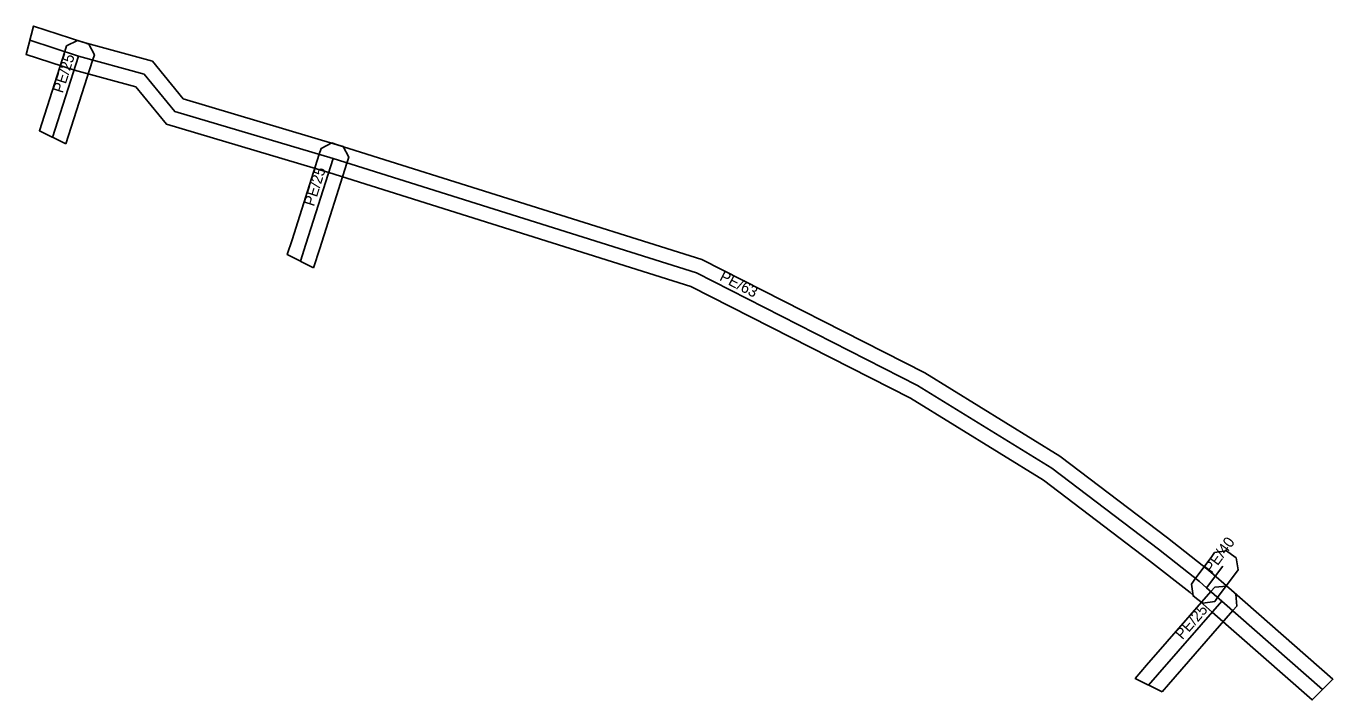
# Model space of a CAD drawing. Extents: x -897856 to -897764, y -995084 to -994957.
# Drawn here: x -897856.1 to -897766.3, y -995083.6 to -995037.3 of the extents above; entities that cross this region are included whole.
import ezdxf

# ---------------------------------------------------------------- set-up
doc = ezdxf.new("R2010")
doc.units = 0
for name, color, linetype in [('1', 7, 'Continuous'), ('24', 7, 'Continuous'), ('30', 7, 'Continuous')]:
    doc.layers.add(name, color=color, linetype=linetype)

msp = doc.modelspace()

# ---------------------------------------------------------------- linework, layer by layer
at = {"layer": '1'}
for points in [[(-897852.817, -995040.308), (-897856.141, -995039.231), (-897855.641, -995037.29), (-897852.243, -995038.392), (-897847.457, -995039.711), (-897845.341, -995042.299), (-897834.748, -995045.444), (-897809.68, -995053.331), (-897794.37, -995061.127), (-897785.074, -995066.864), (-897777.688, -995072.469), (-897774.849, -995074.712), (-897774.332, -995075.167), (-897773.282, -995076.077), (-897766.311, -995082.205), (-897767.728, -995083.622), (-897774.598, -995077.583), (-897775.648, -995076.673), (-897776.131, -995076.248), (-897778.912, -995074.051), (-897786.206, -995068.516), (-897795.35, -995062.873), (-897810.44, -995055.189), (-897835.332, -995047.356), (-897846.499, -995044.041), (-897848.603, -995041.469)], [(-897853.415, -995045.392), (-897855.225, -995044.487), (-897853.482, -995039.045), (-897853.356, -995038.651), (-897852.619, -995038.272), (-897852.225, -995038.398), (-897851.831, -995038.524), (-897851.452, -995039.261), (-897851.578, -995039.655)], [(-897836.38, -995053.91), (-897838.191, -995053.004), (-897837.863, -995051.977), (-897835.993, -995046.097), (-897835.867, -995045.702), (-897835.132, -995045.321), (-897834.737, -995045.447), (-897834.342, -995045.573), (-897833.961, -995046.308), (-897834.087, -995046.703), (-897835.957, -995052.583)], [(-897776.04, -995075.658), (-897775.794, -995075.325), (-897774.684, -995073.825), (-897774.438, -995073.492), (-897773.618, -995073.37), (-897773.285, -995073.616), (-897772.952, -995073.862), (-897772.83, -995074.682), (-897773.076, -995075.015), (-897774.186, -995076.515), (-897774.432, -995076.848), (-897775.252, -995076.97), (-897775.585, -995076.724), (-897775.918, -995076.478)], [(-897778.051, -995083.074), (-897779.897, -995082.152), (-897779.116, -995081.245), (-897774.694, -995076.173), (-897774.422, -995075.861), (-897773.595, -995075.804), (-897773.283, -995076.076), (-897772.971, -995076.348), (-897772.914, -995077.175), (-897773.186, -995077.487), (-897777.604, -995082.555)]]:
    msp.add_lwpolyline(points, close=True, dxfattribs=at)
at = {"layer": '24'}
for points in [[(-897855.891, -995038.261), (-897852.53, -995039.35), (-897848.03, -995040.59), (-897845.92, -995043.17), (-897835.04, -995046.4), (-897810.06, -995054.26), (-897794.86, -995062), (-897785.64, -995067.69), (-897778.3, -995073.26), (-897775.49, -995075.48), (-897774.99, -995075.92), (-897773.94, -995076.83), (-897767.02, -995082.914)], [(-897852.53, -995039.35), (-897854.32, -995044.94)], [(-897835.04, -995046.4), (-897836.91, -995052.28), (-897837.285, -995053.457)], [(-897774.99, -995075.92), (-897773.88, -995074.42)], [(-897773.94, -995076.83), (-897778.36, -995081.9), (-897778.974, -995082.613)]]:
    msp.add_lwpolyline(points, dxfattribs=at)

# ---------------------------------------------------------------- texts
at = {"layer": '30'}
for s, rotation, p in [('PE/25', 72.24365, (-897853.625, -995041.945)), ('PE/25', 72.35792, (-897836.362, -995049.729)), ('PE/63', 333.01433, (-897808.529, -995054.738)), ('PE/40', 53.49856, (-897774.635, -995074.97)), ('PE/25', 48.91825, (-897776.659, -995079.52))]:
    msp.add_text(s, height=0.75, rotation=rotation, dxfattribs=at).set_placement(p)

doc.saveas('drawing.dxf')
